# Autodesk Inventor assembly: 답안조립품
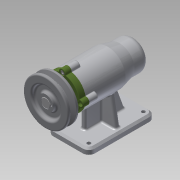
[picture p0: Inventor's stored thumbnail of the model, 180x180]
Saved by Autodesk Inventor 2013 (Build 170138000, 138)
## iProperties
Created: 2019-07
Part Number: 답안조립품
Document SubType Name: Assembly
Designer: Administrator
Author: Administrator
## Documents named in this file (12)
- C:\Users\Administrator\Desktop\490704V1031\답안조립품.iam
- C:\Users\Administrator\Desktop\490704V1031\본체.ipt
- C:\Users\Administrator\Desktop\490704V1031\V벨트풀리.ipt
- C:\Users\Administrator\Desktop\490704V1031\멈춤나사 M3.ipt
- C:\Users\Administrator\Desktop\490704V1031\베어링 6004.ipt
- C:\Users\Administrator\Desktop\490704V1031\베어링 51202.ipt
- C:\Users\Administrator\Desktop\490704V1031\볼트 M4.ipt
- C:\Users\Administrator\Desktop\490704V1031\어댑터슬리브.ipt
- C:\Users\Administrator\Desktop\490704V1031\오일 실.ipt
- C:\Users\Administrator\Desktop\490704V1031\축.ipt
- C:\Users\Administrator\Desktop\490704V1031\커버.ipt
- C:\Users\Administrator\Desktop\490704V1031\키 5 x 5 x 16.ipt
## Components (1 placed, 1 different names)
1. V벨트풀리:2
